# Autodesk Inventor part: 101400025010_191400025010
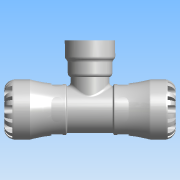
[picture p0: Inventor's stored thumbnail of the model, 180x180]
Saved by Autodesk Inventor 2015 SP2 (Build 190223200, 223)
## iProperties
Created: 2016-12
Part Number: 101400025010_191400025010
Material: PVC-Piping
Description: PLASSON TEE WITH THREADED FEMALE OFFTAKE 25X1" SERIES 1
Document SubType Name: Modeling
Designer: KIM
Mass: 664.223 g
Surface Area: 733.008 cm^2
Volume: 474.445 cm^3
Density: 1.4 g/cm^3
Appearance: Smooth - White
Author: KIM
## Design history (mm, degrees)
derived "1014.ipt"
feature "Solid1::1014.ipt"
tag "TaggingFeature1"
body "Solid1"
other parameters: "d1" = 20.16, "d2" = 25, "d3" = 31.25, "d4" = 47, "d8" = 39.95, "d13" = 6.3, "d14" = 6.3, "d15" = 0, "d17" = 360 deg, "d19" = 8 deg, "d20" = 0.5, "d21" = 0.5, "d22" = 8 deg, "d24" = 0, "d26" = 360 deg, "d33" = 4.7, "d43" = 36.66, "d51" = 0.47, "d54" = 8.75, "d55" = 5.5, "d57" = 12.348, "d58" = 0, "d74" = 0, "d77" = 2.08333, "d78" = 48, "d79" = 36.66, "d80" = 134, "d82" = 0.5, "d115" = 360 deg, "d139" = 6.3, "d140" = 0, "d142" = 360 deg, "d207" = 90 deg, "d228" = 7.4375, "d247" = 0.94, "d248" = 2.88, "d266" = 0, "d268" = 30.291, "d270" = 4.54365, "d271" = 7, "d274" = 2.27183, "d275" = 54, "d276" = 3.0291, "d277" = 3.0291, "d278" = 3.0291, "d279" = 3.0291, "d281" = 0, "d282" = 21, "d_" = 25, "E_" = 47, "l_" = 48, "A_" = 54, "H_" = 134, "Rp_" = 30.291, "l_2" = 21, "d9" = 7.875, "d11" = 47, "d12" = 31.25
